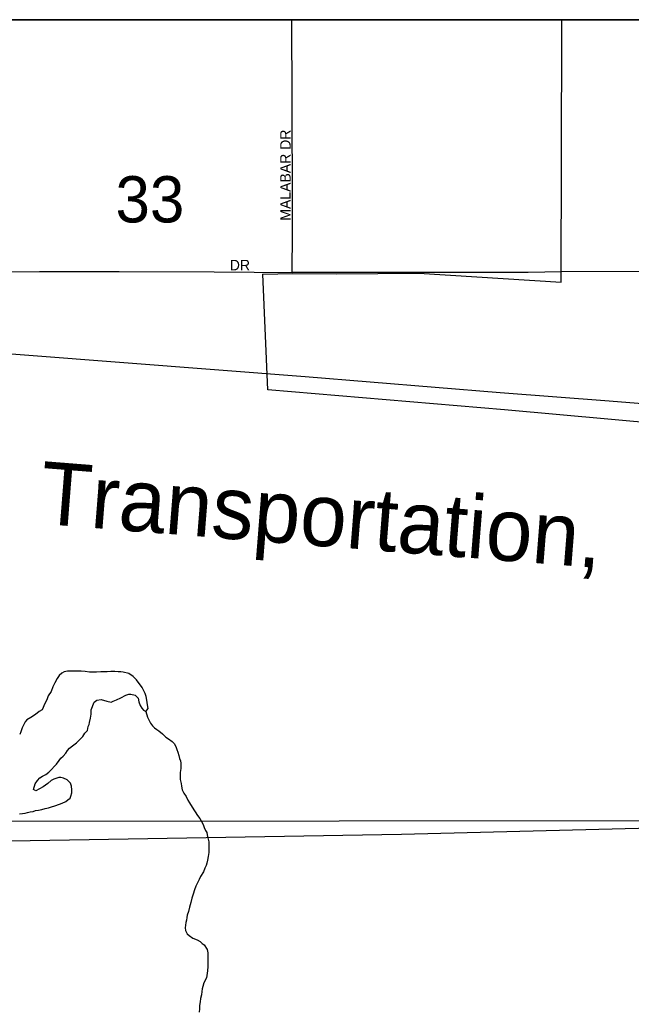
# Model space of a CAD drawing. Extents: x -17 to 88, y -5 to 22.
# Drawn here: x 5.098 to 5.65, y 20.006 to 20.9 of the extents above; entities that cross this region are included whole.
import ezdxf

# ---------------------------------------------------------------- set-up
doc = ezdxf.new("R2010")
doc.units = 0
for name, color, linetype in [('GM_X_City_Street', 7, 'Continuous'), ('GM_X_City_Street_Text', 7, 'Continuous'), ('GM_X_Corporation', 7, 'Continuous'), ('GM_X_County_Road', 7, 'Continuous'), ('GM_X_Minor_Lake', 7, 'Continuous'), ('GM_X_Minor_River', 7, 'Continuous'), ('GM_X_Rail_Line', 7, 'Continuous'), ('GM_X_Rail_Line_Text', 7, 'Continuous'), ('GM_X_Section', 7, 'Continuous'), ('GM_X_Section_Text', 7, 'Continuous'), ('GM_X_Township', 7, 'Continuous'), ('SH_Data', 7, 'Continuous')]:
    doc.layers.add(name, color=color, linetype=linetype)

msp = doc.modelspace()

# ---------------------------------------------------------------- linework, layer by layer
at = {"layer": 'GM_X_City_Street'}
for points in [[(5.34402, 20.67174), (5.34403, 20.67292), (5.34421, 20.70601), (5.34423, 20.75635), (5.34408, 20.80171), (5.34407, 20.83714), (5.3436, 20.88936), (5.3437, 20.9)], [(5.05017, 20.67194), (5.07487, 20.6721), (5.11567, 20.67234), (5.1878, 20.67249), (5.27367, 20.67208), (5.30978, 20.67182), (5.31731, 20.67171)]]:
    msp.add_lwpolyline(points, dxfattribs=at)
at = {"layer": 'GM_X_Corporation'}
msp.add_line((5.58768, 20.9), (3.20786, 20.9), dxfattribs=at)
for points in [[(5.67921, 20.53433), (5.53585, 20.54742), (5.32205, 20.56542), (5.31752, 20.67005), (5.34451, 20.67078), (5.38451, 20.67046), (5.45847, 20.67109), (5.5872, 20.66287), (5.58768, 20.89143), (5.58768, 20.9)], [(5.0718, 20.15737), (5.19586, 20.15958), (5.44295, 20.16396), (5.7163, 20.17066)]]:
    msp.add_lwpolyline(points, dxfattribs=at)
at = {"layer": 'GM_X_County_Road'}
for points in [[(5.31731, 20.67171), (5.34402, 20.67174)], [(5.34402, 20.67174), (5.34666, 20.67174), (5.40368, 20.6719), (5.55723, 20.67199), (5.58736, 20.67235)], [(5.58736, 20.67235), (5.66505, 20.67289), (5.72207, 20.67292)]]:
    msp.add_lwpolyline(points, dxfattribs=at)
at = {"layer": 'GM_X_Minor_Lake'}
for points in [[(5.13507, 20.21495), (5.13317, 20.21496), (5.13127, 20.2146), (5.1286, 20.21348), (5.12631, 20.21236), (5.12326, 20.20973), (5.12097, 20.20823), (5.11906, 20.20672), (5.1122, 20.20298), (5.11031, 20.20413), (5.11186, 20.20943), (5.11378, 20.21245), (5.11608, 20.21471), (5.11837, 20.21621), (5.12142, 20.21771), (5.12409, 20.21996), (5.12639, 20.22223), (5.12906, 20.22524), (5.13098, 20.22712), (5.13328, 20.23052), (5.13481, 20.2324), (5.1371, 20.23428), (5.1394, 20.23692), (5.14094, 20.23957), (5.14285, 20.24145), (5.14553, 20.24371), (5.14896, 20.24633), (5.15202, 20.24935), (5.1547, 20.25198), (5.15662, 20.255), (5.15892, 20.25764), (5.1597, 20.26105), (5.16048, 20.26294), (5.16087, 20.26484), (5.16165, 20.26863), (5.16244, 20.27241), (5.16247, 20.27621), (5.16518, 20.28302), (5.16747, 20.2849), (5.17127, 20.28563), (5.17657, 20.28407), (5.18037, 20.28328), (5.18227, 20.28402), (5.18532, 20.28514), (5.18913, 20.28701), (5.1937, 20.28963), (5.19636, 20.29037), (5.19827, 20.29035), (5.20206, 20.28956), (5.20469, 20.28689), (5.20543, 20.28347), (5.20654, 20.28004), (5.20805, 20.27776), (5.20955, 20.27585), (5.21182, 20.27469), (5.21374, 20.27733), (5.21338, 20.28075), (5.21265, 20.28493), (5.21192, 20.28835), (5.21118, 20.29101), (5.21006, 20.2933), (5.20856, 20.29634), (5.20706, 20.29863), (5.2048, 20.30131), (5.20329, 20.30321), (5.20028, 20.30627), (5.1965, 20.30896), (5.19119, 20.31014), (5.1893, 20.31053), (5.18664, 20.31055), (5.1836, 20.31095), (5.18019, 20.31098), (5.17677, 20.31063), (5.17373, 20.31065), (5.17107, 20.31067), (5.16727, 20.31032), (5.16538, 20.31033), (5.16348, 20.31035), (5.16082, 20.31037), (5.15703, 20.31078), (5.15323, 20.31118), (5.15019, 20.31121), (5.14716, 20.31123), (5.14488, 20.31125), (5.14298, 20.31126), (5.14108, 20.31128), (5.13804, 20.31054), (5.13575, 20.30942), (5.13346, 20.30716), (5.13154, 20.30452), (5.12961, 20.30074), (5.12769, 20.29696), (5.12614, 20.2928), (5.12345, 20.28903), (5.12229, 20.28524), (5.12036, 20.28184), (5.11804, 20.27617), (5.11538, 20.27467), (5.11194, 20.27204), (5.10774, 20.26942), (5.10431, 20.26717)], [(5.10431, 20.26717), (5.10278, 20.26528), (5.10008, 20.25999), (5.09892, 20.2562), (5.09776, 20.25394)], [(5.09762, 20.18222), (5.10028, 20.18258), (5.10256, 20.18295), (5.10484, 20.18331), (5.10712, 20.18405), (5.10978, 20.18441), (5.11207, 20.18515), (5.11473, 20.18551), (5.11777, 20.18624), (5.12081, 20.18698), (5.12385, 20.18771), (5.12652, 20.18845), (5.12956, 20.18957), (5.13375, 20.19105), (5.13603, 20.1918), (5.13946, 20.19329), (5.14137, 20.19479), (5.14328, 20.19629), (5.14406, 20.19819), (5.14484, 20.20121), (5.14486, 20.20387), (5.1445, 20.20729), (5.14376, 20.20995), (5.14074, 20.21301), (5.13734, 20.21455), (5.13507, 20.21495)]]:
    msp.add_lwpolyline(points, dxfattribs=at)
at = {"layer": 'GM_X_Minor_River'}
msp.add_lwpolyline([(5.21182, 20.27469), (5.2133, 20.26975), (5.21442, 20.26708), (5.21592, 20.26404), (5.2178, 20.26174), (5.21968, 20.25983), (5.22157, 20.2583), (5.22346, 20.25715), (5.22686, 20.25447), (5.22988, 20.25141), (5.23214, 20.24987), (5.23554, 20.24757), (5.23743, 20.24566), (5.23893, 20.24299), (5.23967, 20.24033), (5.24079, 20.23805), (5.24153, 20.235), (5.24227, 20.23234), (5.24301, 20.23006), (5.24338, 20.22816), (5.24336, 20.22588), (5.24334, 20.22323), (5.24293, 20.21944), (5.24292, 20.21716), (5.24289, 20.21337), (5.24362, 20.20957), (5.24398, 20.20729), (5.24472, 20.20387), (5.24621, 20.20082), (5.24809, 20.19777), (5.24959, 20.19472), (5.25109, 20.19206), (5.25372, 20.18824), (5.2586, 20.18062), (5.26048, 20.17795), (5.26198, 20.17528), (5.26347, 20.17261), (5.2646, 20.16995), (5.26571, 20.16728), (5.26684, 20.16538), (5.2672, 20.16309), (5.26794, 20.16043), (5.26868, 20.15701), (5.26866, 20.15474), (5.26863, 20.15094), (5.2686, 20.14715), (5.2682, 20.14374), (5.26742, 20.14033), (5.26702, 20.13768), (5.26624, 20.13541), (5.26509, 20.13314), (5.26392, 20.12973), (5.26123, 20.12558), (5.26007, 20.12293), (5.25853, 20.11991), (5.25699, 20.11688), (5.25583, 20.11348), (5.25466, 20.10969), (5.25349, 20.10591), (5.25233, 20.10212), (5.25116, 20.09796), (5.25037, 20.09379), (5.24921, 20.09076), (5.24881, 20.08849), (5.24842, 20.08622), (5.24802, 20.08394), (5.24762, 20.08167), (5.24722, 20.07902), (5.24759, 20.07674), (5.24908, 20.07369), (5.25097, 20.07216), (5.25437, 20.06985), (5.25816, 20.06831), (5.2608, 20.06677), (5.26269, 20.06486), (5.26458, 20.06371), (5.26721, 20.05951), (5.26794, 20.05647), (5.26785, 20.04433), (5.26745, 20.04016), (5.26664, 20.03409), (5.26433, 20.02956), (5.26317, 20.02615), (5.26277, 20.02388), (5.26237, 20.02161), (5.26197, 20.01858), (5.26119, 20.01517), (5.26078, 20.01213), (5.26038, 20.0091), (5.26036, 20.00607), (5.25996, 20.00303)], dxfattribs=at)
at = {"layer": 'GM_X_Rail_Line'}
msp.add_lwpolyline([(3.33784, 20.63494), (3.42428, 20.63515), (3.66767, 20.63326), (4.04986, 20.62913), (4.41143, 20.62553), (4.69708, 20.62244), (4.78173, 20.62035), (4.83124, 20.61775), (4.87795, 20.61471), (5.02378, 20.6032), (5.35564, 20.57743), (5.53204, 20.56318), (5.63047, 20.55545), (5.71669, 20.54875), (6.32595, 20.50065), (6.53551, 20.48433), (6.65266, 20.47472), (6.95205, 20.45153), (7.27068, 20.42662), (7.45962, 20.41202), (8.17109, 20.35637), (8.73122, 20.31274), (9.05827, 20.28714), (9.4, 20.26034)], dxfattribs=at)
at = {"layer": 'GM_X_Section'}
msp.add_line((5.72144, 20.9), (4.71178, 20.9), dxfattribs=at)
msp.add_lwpolyline([(4.71178, 20.9), (4.7146, 20.17531), (5.72232, 20.1762), (5.72144, 20.9)], dxfattribs=at)
msp.add_lwpolyline([(5.72232, 20.1762), (5.72057, 19.1483), (4.72971, 19.15674), (4.7146, 20.17531)], close=True, dxfattribs=at)
at = {"layer": 'GM_X_Township'}
msp.add_line((7.72185, 20.9), (2.68822, 20.9), dxfattribs=at)
at = {"layer": 'SH_Data'}
msp.add_line((2.6, 20.9), (9.4, 20.9), dxfattribs=at)

# ---------------------------------------------------------------- texts
at = {"layer": 'GM_X_City_Street_Text'}
for s, rotation, p in [('MALABAR DR', 90, (5.34266, 20.71841)), ('DR', 0.00001, (5.28765, 20.67352))]:
    msp.add_text(s, height=0.00947, rotation=rotation, dxfattribs=at).set_placement(p)
at = {"layer": 'GM_X_Rail_Line_Text'}
msp.add_text('Transportation,', height=0.0566288, rotation=355.46115, dxfattribs=at).set_placement((5.11458, 20.44458))
at = {"layer": 'GM_X_Section_Text'}
msp.add_text('33', height=0.041856, rotation=0.00001, dxfattribs=at).set_placement((5.18432, 20.7168))

doc.saveas('drawing.dxf')
